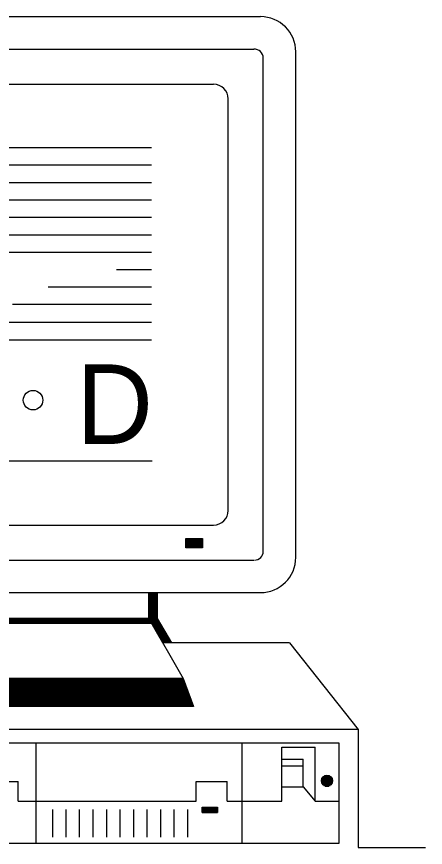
# Model space of a CAD drawing. Extents: x 0 to 53.3, y -0.3 to 37.1.
# Drawn here: x 42.432 to 43.452, y 1.925 to 3.997 of the extents above; entities that cross this region are included whole.
import ezdxf

# ---------------------------------------------------------------- set-up
doc = ezdxf.new("R2010")
doc.units = 0
for name, color, linetype in [('Level 1', 7, 'Continuous'), ('Level 25', 7, 'Continuous'), ('Level 50', 7, 'Continuous')]:
    doc.layers.add(name, color=color, linetype=linetype)

msp = doc.modelspace()

# ---------------------------------------------------------------- linework, layer by layer
at = {"layer": 'Level 1'}
for p, q in [((41.8253, 3.6705), (42.7686, 3.6705)), ((42.3839, 3.6269), (42.7686, 3.6269)), ((42.3839, 3.5834), (42.7686, 3.5834)), ((42.3839, 3.5399), (42.7686, 3.5399)), ((42.3839, 3.4962), (42.7686, 3.4962)), ((42.3839, 3.4525), (42.7686, 3.4525)), ((41.8253, 3.4089), (42.7686, 3.4089)), ((42.7684, 3.3655), (42.6813, 3.3655)), ((42.7684, 3.3219), (42.5114, 3.3219)), ((42.7684, 3.2784), (42.4221, 3.2784)), ((41.8253, 3.2347), (42.7686, 3.2347)), ((41.8253, 3.191), (42.7686, 3.191)), ((41.8253, 2.8885), (42.7703, 2.8885))]:
    msp.add_line(p, q, dxfattribs=at)
msp.add_circle((42.4734, 3.0401), 0.0244, dxfattribs=at)
at = {"layer": 'Level 25'}
for p, q in [((43.1286, 2.648), (43.1286, 3.9089)), ((43.0474, 2.6634), (43.0474, 3.8937)), ((42.9601, 2.7652), (42.9601, 3.7917)), ((41.6618, 2.7285), (42.9234, 2.7285)), ((42.8543, 2.694), (42.8961, 2.694)), ((42.8543, 2.6929), (42.8961, 2.6929)), ((42.8543, 2.6915), (42.8961, 2.6915)), ((42.8543, 2.69), (42.8961, 2.69)), ((42.8543, 2.6887), (42.8961, 2.6887)), ((42.8543, 2.6875), (42.8961, 2.6875)), ((42.8543, 2.6862), (42.8961, 2.6862)), ((42.8543, 2.6849), (42.8961, 2.6849)), ((42.8543, 2.6835), (42.8961, 2.6835)), ((42.8543, 2.6822), (42.8961, 2.6822)), ((42.8543, 2.6809), (42.8961, 2.6809)), ((42.8543, 2.6795), (42.8961, 2.6795)), ((42.8543, 2.6784), (42.8961, 2.6784)), ((42.8543, 2.6769), (42.8961, 2.6769)), ((42.8543, 2.6755), (42.8961, 2.6755)), ((42.8543, 2.6744), (42.8961, 2.6744)), ((42.8543, 2.673), (42.8961, 2.673)), ((41.5598, 2.6414), (43.0239, 2.6414)), ((41.5446, 2.56), (43.0406, 2.56)), ((42.7619, 2.4954), (42.7619, 2.56)), ((42.7831, 2.5595), (42.7619, 2.5595)), ((42.7831, 2.5582), (42.7619, 2.5582)), ((42.7831, 2.557), (42.7619, 2.557)), ((42.7831, 2.5555), (42.7619, 2.5555)), ((42.7831, 2.5542), (42.7619, 2.5542)), ((42.7831, 2.5529), (42.7619, 2.5529)), ((42.7831, 2.5517), (42.7619, 2.5517)), ((42.7831, 2.5504), (42.7619, 2.5504)), ((42.7831, 2.4954), (42.7831, 2.56)), ((42.7831, 2.5489), (42.7619, 2.5489)), ((42.7831, 2.5475), (42.7619, 2.5475)), ((42.7831, 2.5464), (42.7619, 2.5464)), ((42.7831, 2.545), (42.7619, 2.545)), ((42.7831, 2.5437), (42.7619, 2.5437)), ((42.7831, 2.5424), (42.7619, 2.5424)), ((42.7831, 2.541), (42.7619, 2.541)), ((42.7831, 2.5397), (42.7619, 2.5397)), ((42.7831, 2.5384), (42.7619, 2.5384)), ((42.7831, 2.5372), (42.7619, 2.5372)), ((42.7831, 2.5357), (42.7619, 2.5357)), ((42.7831, 2.5344), (42.7619, 2.5344)), ((42.7831, 2.5332), (42.7619, 2.5332)), ((42.7831, 2.5319), (42.7619, 2.5319)), ((42.7831, 2.5305), (42.7619, 2.5305)), ((42.7831, 2.529), (42.7619, 2.529)), ((42.7831, 2.5279), (42.7619, 2.5279)), ((42.7831, 2.5265), (42.7619, 2.5265)), ((42.7831, 2.5252), (42.7619, 2.5252)), ((42.7831, 2.524), (42.7619, 2.524)), ((42.7831, 2.5225), (42.7619, 2.5225)), ((42.7831, 2.5212), (42.7619, 2.5212)), ((42.7831, 2.5199), (42.7619, 2.5199)), ((42.7831, 2.5187), (42.7619, 2.5187)), ((42.7831, 2.5174), (42.7619, 2.5174)), ((42.7831, 2.5159), (42.7619, 2.5159)), ((42.7831, 2.5145), (42.7619, 2.5145)), ((42.7831, 2.5134), (42.7619, 2.5134)), ((42.7831, 2.512), (42.7619, 2.512)), ((42.7831, 2.5107), (42.7619, 2.5107)), ((42.7831, 2.5094), (42.7619, 2.5094)), ((42.7831, 2.508), (42.7619, 2.508)), ((42.7619, 2.4954), (42.2926, 2.4954)), ((42.7623, 2.495), (42.2926, 2.495)), ((42.7631, 2.4937), (42.2926, 2.4937)), ((42.7638, 2.4924), (42.2926, 2.4924)), ((42.7644, 2.491), (42.2926, 2.491)), ((42.7653, 2.4897), (42.2926, 2.4897)), ((42.7659, 2.4884), (42.2926, 2.4884)), ((42.7668, 2.487), (42.2926, 2.487)), ((42.7831, 2.5067), (42.7619, 2.5067)), ((42.7831, 2.5054), (42.7619, 2.5054)), ((42.7831, 2.5042), (42.7619, 2.5042)), ((42.7831, 2.5027), (42.7619, 2.5027)), ((42.7831, 2.5014), (42.7619, 2.5014)), ((42.7831, 2.5002), (42.7619, 2.5002)), ((42.7831, 2.4989), (42.7619, 2.4989)), ((42.7831, 2.4975), (42.7619, 2.4975)), ((42.7831, 2.496), (42.7619, 2.496)), ((42.7619, 2.4954), (42.8478, 2.3459)), ((42.7834, 2.4949), (42.7623, 2.4949)), ((42.7841, 2.4935), (42.7631, 2.4935)), ((42.7851, 2.4922), (42.7638, 2.4922)), ((42.7858, 2.491), (42.7648, 2.491)), ((42.7864, 2.4895), (42.7654, 2.4895)), ((42.7873, 2.4882), (42.7661, 2.4882)), ((42.7879, 2.4869), (42.7669, 2.4869)), ((42.7831, 2.4954), (42.8183, 2.4344)), ((42.7676, 2.4859), (42.2926, 2.4859)), ((42.7684, 2.4844), (42.2926, 2.4844)), ((42.7691, 2.483), (42.2926, 2.483)), ((42.7693, 2.4829), (42.2926, 2.4829)), ((42.7888, 2.4857), (42.7676, 2.4857)), ((42.7896, 2.4844), (42.7684, 2.4844)), ((42.7901, 2.4829), (42.7691, 2.4829)), ((42.7911, 2.4815), (42.7698, 2.4815)), ((42.7918, 2.4804), (42.7708, 2.4804)), ((42.7926, 2.479), (42.7714, 2.479)), ((42.7933, 2.4777), (42.7723, 2.4777)), ((42.7941, 2.4764), (42.7729, 2.4764)), ((42.7948, 2.475), (42.7736, 2.475)), ((42.7956, 2.4737), (42.7744, 2.4737)), ((42.7964, 2.4724), (42.7753, 2.4724)), ((42.7971, 2.4712), (42.7759, 2.4712)), ((42.7979, 2.4697), (42.7768, 2.4697)), ((42.7986, 2.4684), (42.7776, 2.4684)), ((42.7993, 2.4672), (42.7783, 2.4672)), ((42.8001, 2.4659), (42.7789, 2.4659)), ((42.8008, 2.4645), (42.7798, 2.4645)), ((42.8018, 2.463), (42.7804, 2.463)), ((42.8024, 2.4619), (42.7814, 2.4619)), ((42.8033, 2.4605), (42.7821, 2.4605)), ((42.8039, 2.4592), (42.7828, 2.4592)), ((42.8046, 2.458), (42.7836, 2.458)), ((42.8054, 2.4565), (42.7843, 2.4565)), ((42.8061, 2.4552), (42.7851, 2.4552)), ((42.8069, 2.4539), (42.7858, 2.4539)), ((42.8078, 2.4527), (42.7864, 2.4527)), ((42.8084, 2.4514), (42.7874, 2.4514)), ((42.8093, 2.4499), (42.7881, 2.4499)), ((42.8099, 2.4485), (42.7889, 2.4485)), ((42.8108, 2.4474), (42.7896, 2.4474)), ((42.8114, 2.446), (42.7904, 2.446)), ((42.8121, 2.4447), (42.7911, 2.4447)), ((42.8131, 2.4434), (42.7918, 2.4434)), ((42.8138, 2.442), (42.7926, 2.442)), ((42.8146, 2.4407), (42.7934, 2.4407)), ((42.8153, 2.4394), (42.7943, 2.4394)), ((42.8161, 2.4382), (42.7949, 2.4382)), ((42.8168, 2.4367), (42.7956, 2.4367)), ((42.8174, 2.4354), (42.7964, 2.4354)), ((43.1128, 2.4344), (43.2841, 2.2182)), ((42.8479, 2.3454), (42.2926, 2.3454)), ((42.8484, 2.344), (42.2926, 2.344)), ((42.8491, 2.3429), (42.2926, 2.3429)), ((42.8494, 2.3414), (42.2926, 2.3414)), ((42.8499, 2.34), (42.2926, 2.34)), ((42.8504, 2.3389), (42.2926, 2.3389)), ((42.8509, 2.3375), (42.2926, 2.3375)), ((42.8514, 2.3362), (42.2926, 2.3362)), ((42.8518, 2.3347), (42.2926, 2.3347)), ((42.8523, 2.3335), (42.2926, 2.3335)), ((42.8529, 2.3322), (42.2926, 2.3322)), ((42.8534, 2.3309), (42.2926, 2.3309)), ((42.8538, 2.3297), (42.2926, 2.3297)), ((42.8543, 2.3282), (42.2926, 2.3282)), ((42.8549, 2.3269), (42.2926, 2.3269)), ((42.8553, 2.3255), (42.2926, 2.3255)), ((42.8558, 2.3244), (42.2926, 2.3244)), ((42.8561, 2.323), (42.2926, 2.323)), ((42.8568, 2.3215), (42.2926, 2.3215)), ((42.8573, 2.3202), (42.2926, 2.3202)), ((42.8578, 2.319), (42.2926, 2.319)), ((42.8583, 2.3177), (42.2926, 2.3177)), ((42.8588, 2.3164), (42.2926, 2.3164)), ((42.8591, 2.315), (42.2926, 2.315)), ((42.8596, 2.3137), (42.2926, 2.3137)), ((42.8603, 2.3124), (42.2926, 2.3124)), ((42.8606, 2.311), (42.2926, 2.311)), ((42.8611, 2.3099), (42.2926, 2.3099)), ((42.8616, 2.3084), (42.2926, 2.3084)), ((42.8623, 2.307), (42.2926, 2.307)), ((42.8626, 2.3059), (42.2926, 2.3059)), ((42.8631, 2.3045), (42.2926, 2.3045)), ((42.8634, 2.3032), (42.2926, 2.3032)), ((42.8641, 2.3017), (42.2926, 2.3017)), ((42.8646, 2.3005), (42.2926, 2.3005)), ((42.8649, 2.2992), (42.2926, 2.2992)), ((42.8656, 2.2979), (42.2926, 2.2979)), ((42.8661, 2.2967), (42.2926, 2.2967)), ((42.8664, 2.2952), (42.2926, 2.2952)), ((42.8669, 2.2939), (42.2926, 2.2939)), ((42.8676, 2.2925), (42.2926, 2.2925)), ((42.8679, 2.2914), (42.2926, 2.2914)), ((42.8684, 2.29), (42.2926, 2.29)), ((42.8689, 2.2885), (42.2926, 2.2885)), ((42.8694, 2.2872), (42.2926, 2.2872)), ((42.8699, 2.286), (42.2926, 2.286)), ((42.8704, 2.2847), (42.2926, 2.2847)), ((42.8708, 2.2834), (42.2926, 2.2834)), ((42.8714, 2.282), (42.2926, 2.282)), ((42.8719, 2.2807), (42.2926, 2.2807)), ((42.8723, 2.2794), (42.2926, 2.2794)), ((42.8729, 2.278), (42.2926, 2.278)), ((42.8734, 2.2769), (42.2926, 2.2769)), ((43.2841, 2.2182), (42.2926, 2.2182)), ((43.2841, 2.2182), (43.2841, 1.9245)), ((42.4809, 1.9342), (42.4809, 2.185)), ((42.9944, 1.9342), (42.9944, 2.185)), ((43.0936, 2.0397), (43.0936, 2.1742)), ((43.0936, 2.1742), (43.1764, 2.1742)), ((43.1764, 2.0397), (43.1764, 2.1742)), ((43.0936, 2.145), (43.1471, 2.145)), ((43.1471, 2.0752), (43.1471, 2.145)), ((43.0936, 2.1282), (43.1471, 2.1282)), ((43.1926, 2.0935), (43.2199, 2.0935)), ((43.1929, 2.0947), (43.2198, 2.0947)), ((43.1933, 2.096), (43.2191, 2.096)), ((43.1941, 2.0974), (43.2186, 2.0974)), ((43.1948, 2.0989), (43.2178, 2.0989)), ((43.1959, 2.1), (43.2166, 2.1)), ((43.1971, 2.1014), (43.2153, 2.1014)), ((43.1989, 2.1027), (43.2134, 2.1027)), ((43.2021, 2.1039), (43.2106, 2.1039)), ((42.3373, 2.0892), (42.4361, 2.0892)), ((42.4361, 2.0397), (42.4361, 2.0892)), ((42.8803, 2.0892), (42.9576, 2.0892)), ((42.8803, 2.0397), (42.8803, 2.0892)), ((42.9576, 2.0397), (42.9576, 2.0892)), ((43.0936, 2.0752), (43.1471, 2.0752)), ((43.1471, 2.0752), (43.1764, 2.0397)), ((43.1923, 2.0907), (43.2203, 2.0907)), ((43.1924, 2.0922), (43.2201, 2.0922)), ((43.1924, 2.0895), (43.2203, 2.0895)), ((43.1926, 2.0882), (43.2199, 2.0882)), ((43.1928, 2.0869), (43.2198, 2.0869)), ((43.1933, 2.0855), (43.2191, 2.0855)), ((43.1939, 2.0842), (43.2186, 2.0842)), ((43.1946, 2.0829), (43.2179, 2.0829)), ((43.1958, 2.0815), (43.2168, 2.0815)), ((43.1969, 2.0804), (43.2154, 2.0804)), ((43.1988, 2.079), (43.2139, 2.079)), ((43.2014, 2.0775), (43.2111, 2.0775)), ((42.4361, 2.0397), (42.8798, 2.0397)), ((42.9576, 2.0397), (43.0936, 2.0397)), ((43.1764, 2.0397), (43.2361, 2.0397)), ((42.5223, 1.9502), (42.5223, 2.0192)), ((42.5559, 1.9502), (42.5559, 2.0192)), ((42.5896, 1.9502), (42.5896, 2.0192)), ((42.6233, 1.9502), (42.6233, 2.0192)), ((42.6571, 1.9502), (42.6571, 2.0192)), ((42.6908, 1.9502), (42.6908, 2.0192)), ((42.7246, 1.9502), (42.7246, 2.0192)), ((42.7583, 1.9502), (42.7583, 2.0192)), ((42.7918, 1.9502), (42.7918, 2.0192)), ((42.8256, 1.9502), (42.8256, 2.0192)), ((42.8593, 1.9502), (42.8593, 2.0192)), ((42.8954, 2.025), (42.9331, 2.025)), ((42.8954, 2.0239), (42.9331, 2.0239)), ((42.8954, 2.0224), (42.9331, 2.0224)), ((42.8954, 2.021), (42.9331, 2.021)), ((42.8954, 2.0199), (42.9331, 2.0199)), ((42.8954, 2.0185), (42.9331, 2.0185)), ((42.8954, 2.0172), (42.9331, 2.0172)), ((42.8954, 2.0157), (42.9331, 2.0157)), ((42.8954, 2.0145), (42.9331, 2.0145)), ((42.8954, 2.0132), (42.9331, 2.0132)), ((42.8954, 2.0119), (42.9331, 2.0119)), ((43.2841, 1.9245), (43.4516, 1.9245))]:
    msp.add_line(p, q, dxfattribs=at)
for points in [[(42.8543, 2.695), (42.8961, 2.695), (42.8961, 2.6719), (42.8543, 2.6719)], [(42.7831, 2.56), (42.7831, 2.4954), (42.8183, 2.4344), (42.7971, 2.4344), (42.7619, 2.4954), (42.7619, 2.56)], [(42.7619, 2.4954), (42.7693, 2.4829), (42.2926, 2.4829), (42.2926, 2.4954)], [(42.8478, 2.3459), (42.8738, 2.2757), (42.2926, 2.2757), (42.2926, 2.3459)], [(41.3521, 2.185), (43.2361, 2.185), (43.2361, 1.9342), (41.3521, 1.9342)], [(42.8954, 2.025), (42.9331, 2.025), (42.9331, 2.0119), (42.8954, 2.0119)]]:
    msp.add_lwpolyline(points, close=True, dxfattribs=at)
msp.add_circle((43.2063, 2.0907), 0.014, dxfattribs=at)
for centre, start, end in [((43.0254, 3.8936), 0, 93.8704), ((43.0254, 2.6632), 270, 0)]:
    msp.add_arc(centre, 0.022, start, end, dxfattribs=at)
at = {"layer": 'Level 50'}
for p, q in [((41.5446, 3.9969), (43.0406, 3.9969)), ((41.5598, 3.9157), (43.0239, 3.9157)), ((41.6618, 3.8284), (42.9234, 3.8284)), ((43.1128, 2.4344), (42.7971, 2.4344)), ((42.8478, 2.3459), (42.2926, 2.3459)), ((42.8738, 2.2757), (42.2926, 2.2757))]:
    msp.add_line(p, q, dxfattribs=at)
for centre, radius, start, end in [((43.0405, 3.9088), 0.088, 0, 90), ((42.9234, 3.7916), 0.0367, 0, 90), ((42.9234, 2.7652), 0.0367, 270, 0), ((43.0405, 2.648), 0.088, 270, 0)]:
    msp.add_arc(centre, radius, start, end, dxfattribs=at)

# ---------------------------------------------------------------- texts
at = {"layer": 'Level 1'}
msp.add_text('D', height=0.1984, dxfattribs=at).set_placement((42.5808, 2.931))

doc.saveas('drawing.dxf')
